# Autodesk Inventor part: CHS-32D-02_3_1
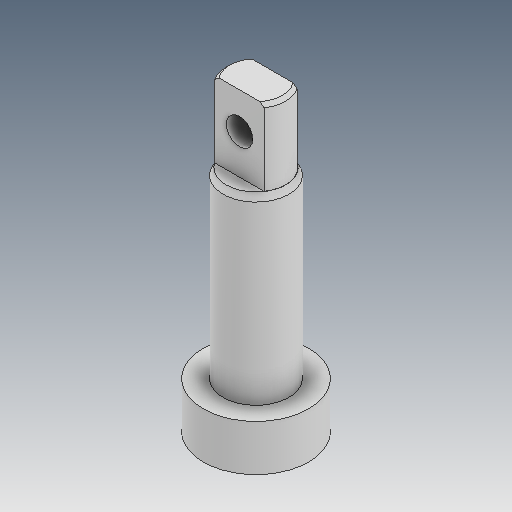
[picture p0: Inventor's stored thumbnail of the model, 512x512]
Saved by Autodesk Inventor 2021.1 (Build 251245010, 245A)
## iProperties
Created: 2021-05
Part Number: CHS-32D-02_3_1
Material: Ogólny
Document SubType Name: Modeling
Designer: user
Density: 1 g/cm^3
Appearance: Domyślna
Author: user
Revision Number: ÈÎºÎ
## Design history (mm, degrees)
feature "ÊäÈë1"
feature "ÊäÈë2"
node "Bryła1"
node "Bryła2"
